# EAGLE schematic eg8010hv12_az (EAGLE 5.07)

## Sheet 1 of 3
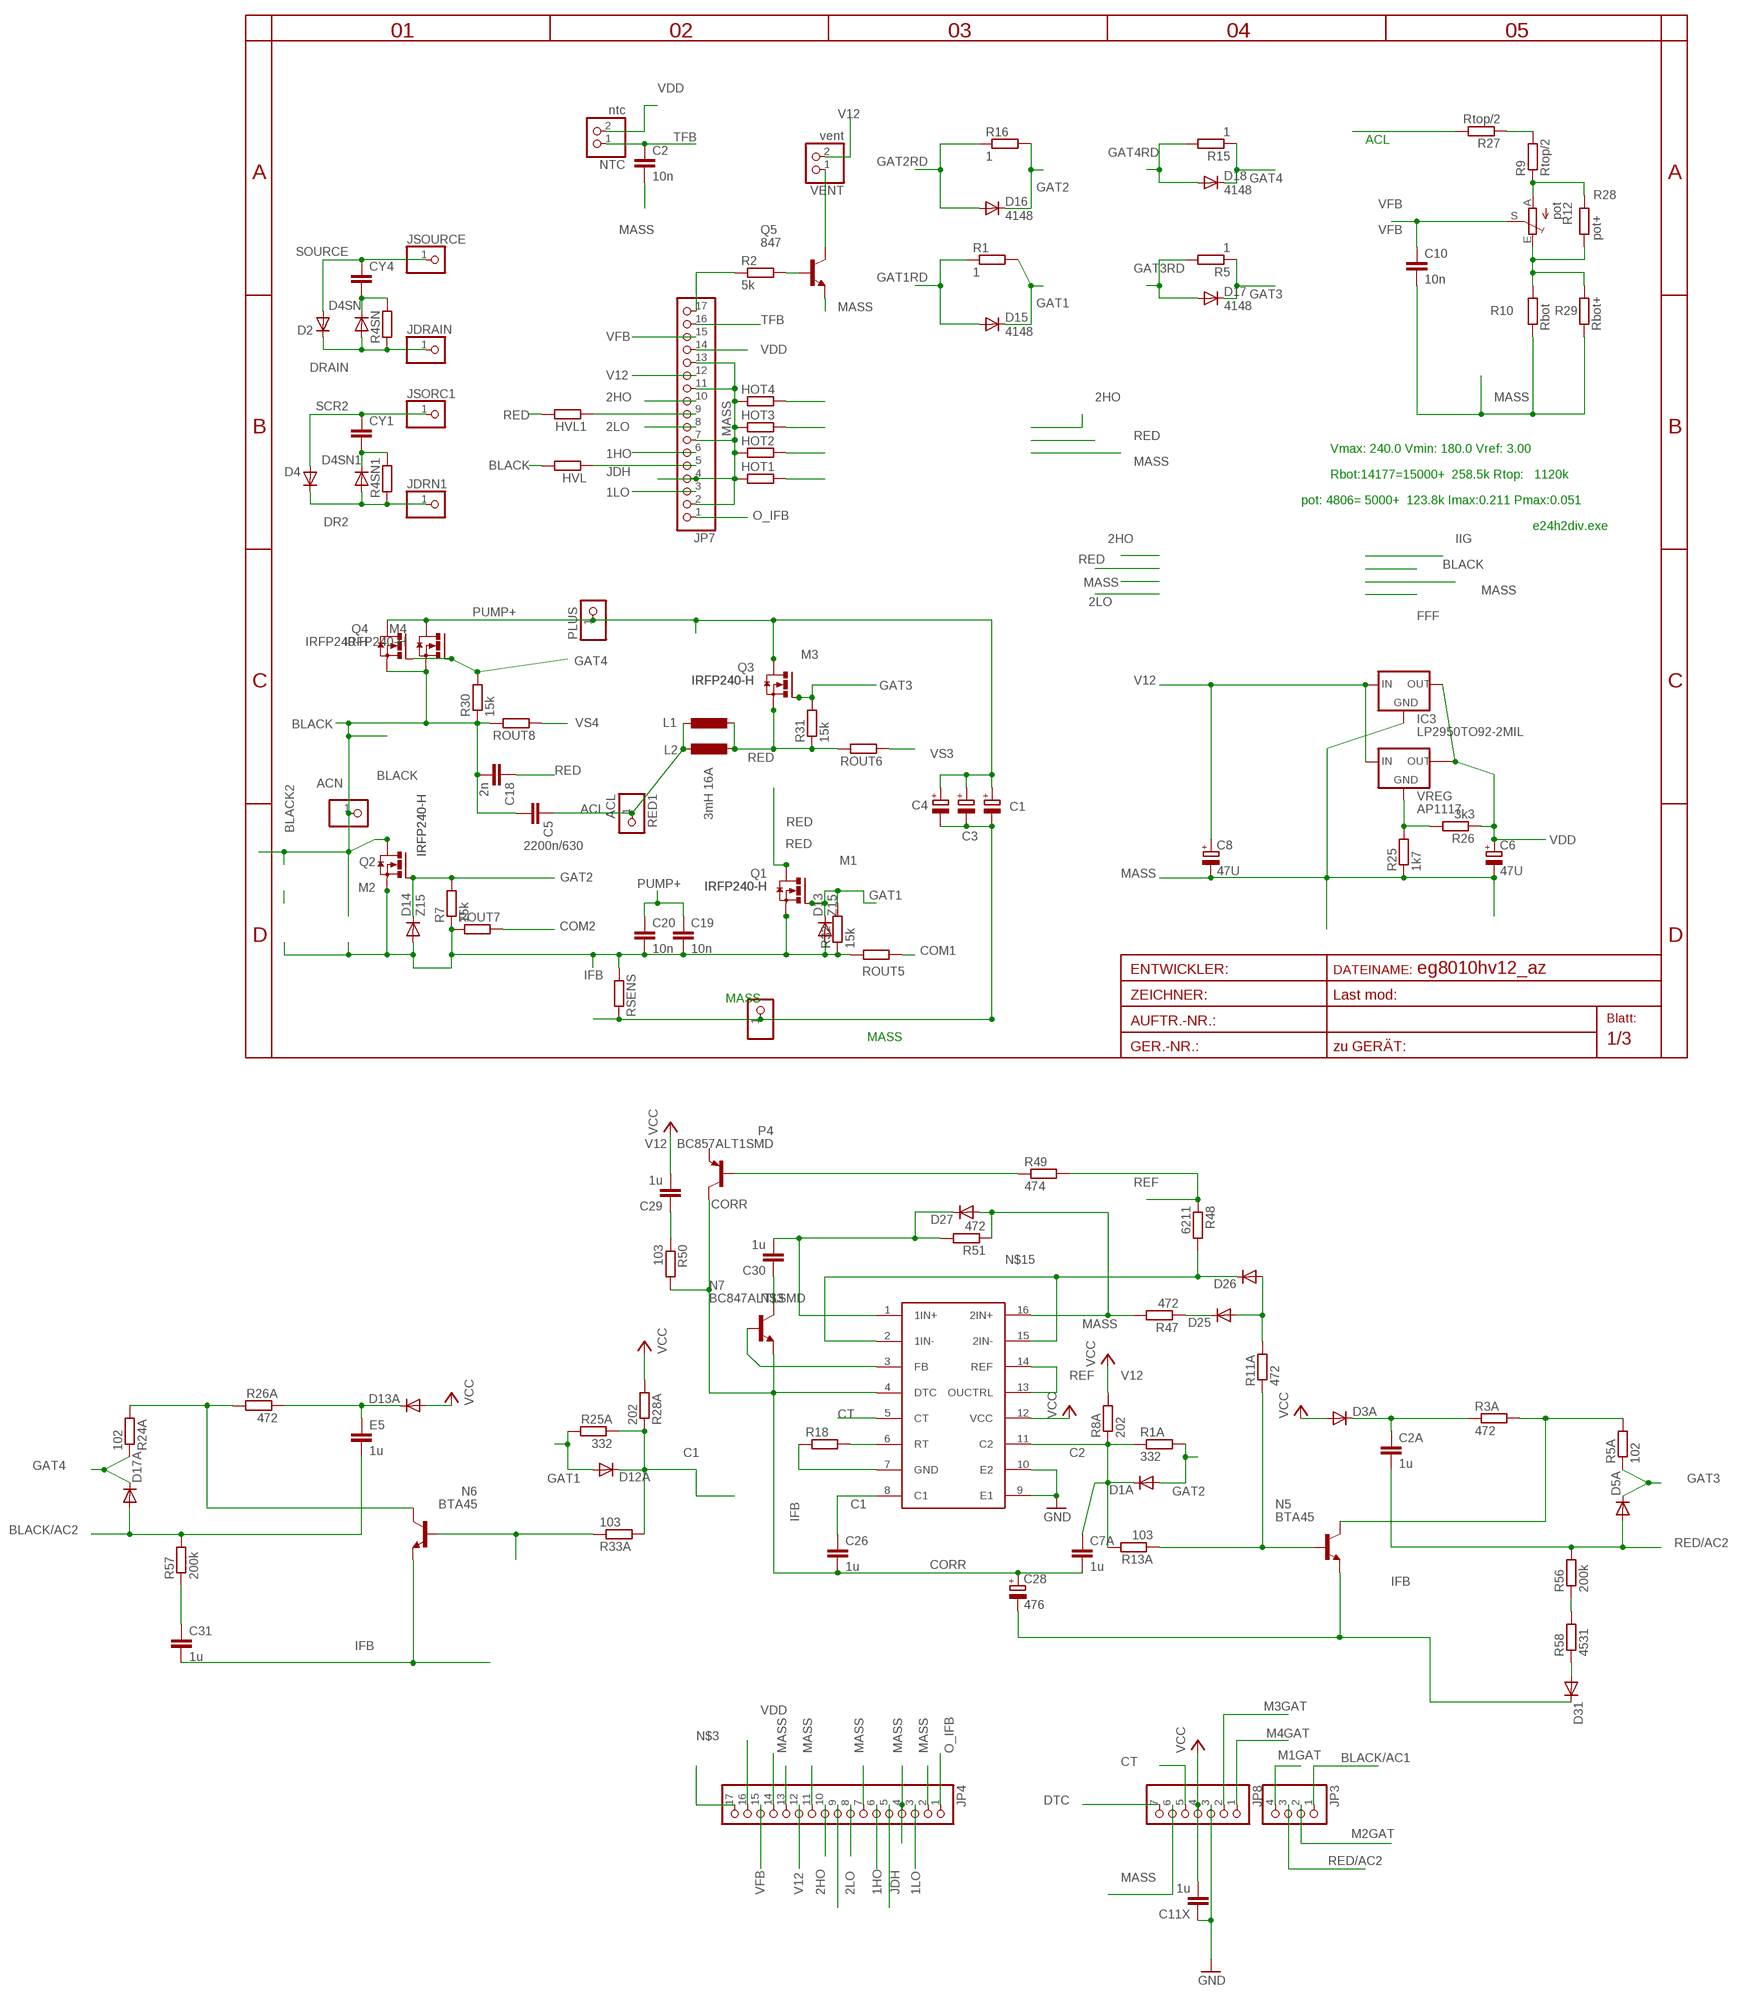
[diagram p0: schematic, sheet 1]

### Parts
BLACK2  ACN  PINHD-1X12MM3  [1X2MM3]
C1  CPOL-EUE5-13  [E5-13]
C2  10n  C-EUC0805  [C0805]
C2A  1u  C-EUC1206  [C1206]
C3  CPOL-EUE5-13  [E5-13]
C4  CPOL-EUE5-13  [E5-13]
C5  2200n/630  C-EU275-173X316  [C275-173X316]
C6  47U  CPOL-EUSMCA  [SMC_A]
C7A  1u  C-EUC0805  [C0805]
C8  47U  CPOL-EUSMCA  [SMC_A]
C10  10n  C-EUC0805  [C0805]
C11X  1u  C-EUC1206  [C1206]
C18  2n  C-EU050-024X044  [C050-024X044]
C19  10n  C-EU050-024X044  [C050-024X044]
C20  10n  C-EU050-024X044  [C050-024X044]
C26  1u  C-EUC0805  [C0805]
C28  476  CPOL-EUD  [PANASONIC_D]
C29  1u  C-EUC0805  [C0805]
C30  1u  C-EUC0805  [C0805]
C31  1u  C-EUC1206  [C1206]
CY1  CXXC10B5  [XC10B5]
CY4  CXXC10B5  [XC10B5]
D1A  DIODE-MINIMELF  [MINIMELF]
D2  DIODE-SMC  [SMC]
D3A  DIODE-SMA-DO214  [SMA-DO214AC]
D4  DIODE-SMC  [SMC]
D4SN  DIODE-P1-10  [P1-10]
D4SN1  DIODE-P1-10  [P1-10]
D5A  DIODE-MINIMELF  [MINIMELF]
D12A  DIODE-MINIMELF  [MINIMELF]
D13  Z15  DIODE-MINIMELF  [MINIMELF]
D13A  DIODE-SMA-DO214  [SMA-DO214AC]
D14  Z15  DIODE-MINIMELF  [MINIMELF]
D15  4148  DIODE-MINIMELF  [MINIMELF]
D16  4148  DIODE-MINIMELF  [MINIMELF]
D17  4148  DIODE-MINIMELF  [MINIMELF]
D17A  DIODE-MINIMELF  [MINIMELF]
D18  4148  DIODE-MINIMELF  [MINIMELF]
D25  DIODE-MINIMELF  [MINIMELF]
D26  DIODE-MINIMELF  [MINIMELF]
D27  DIODE-MINIMELF  [MINIMELF]
D31  DIODE-MINIMELF  [MINIMELF]
E5  1u  C-EUC1206  [C1206]
HOT1  R-EU_R0805  [R0805]
HOT2  R-EU_R0805  [R0805]
HOT3  R-EU_R0805  [R0805]
HOT4  R-EU_R0805  [R0805]
HVL  R-EU_R1005  [R1005]
HVL1  R-EU_R1005  [R1005]
IC3  LP2950TO92-2MIL  [TO92-2MIL]
JDRAIN  PINHD-1X11MM0  [1X1MM0]
JDRN1  PINHD-1X11MM0  [1X1MM0]
JP3  PINHD-1X4  [1X04]
JP4  PINHD-1X17  [1X17]
JP7  PINHD-1X17  [1X17]
JP8  PINHD-1X7  [1X07]
JSORC1  PINHD-1X11MM0  [1X1MM0]
JSOURCE  PINHD-1X11MM0  [1X1MM0]
L1  L-EU4.13  [0204/13]
L2  3mH 16A  L-EURNG  [RING]
M1  IRFP240-H  [TO247BH]
M2  IRFP240-H  [TO247BH]
M3  IRFP240-H  [TO247BH]
M4  IRFP240-H  [TO247BH]
MINUS  PINHD-1X12MM3  [1X2MM3]
N5  BTA45  SMBTA45HV  [SOT23HV]
N6  BTA45  SMBTA45HV  [SOT23HV]
N7  BC847ALT1SMD  [SOT23]
NTC  ntc  PINHD-1X2STR  [1X02]
P4  BC857ALT1SMD  [SOT23-BEC]
PLUS  PINHD-1X12MM3  [1X2MM3]
Q1  IRFP240-H  [TO247BH]
Q2  IRFP240-H  [TO247BH]
Q3  IRFP240-H  [TO247BH]
Q4  IRFP240-H  [TO247BH]
Q5  847  BC847SMD  [SOT23]
R1  1  R-EU_R2512  [R2512]
R1A  332  R-EU_R0805  [R0805]
R2  5k  R-EU_R0805  [R0805]
R3A  472  R-EU_R0805  [R0805]
R4SN  R-EU_0207/10  [0207/10]
R4SN1  R-EU_0207/10  [0207/10]
R5  1  R-EU_R2512  [R2512]
R5A  102  R-EU_R1206  [R1206]
R7  15k  R-EU_R1206  [R1206]
R8A  202  R-EU_R0805  [R0805]
R9  Rtop/2  R-EU_R1206  [R1206]
R10  Rbot  R-EU_R0805  [R0805]
R11A  472  R-EU_R0805  [R0805]
R12  pot  TRIM_EU-B64Y  [B64Y]
R13A  103  R-EU_0207/15  [0207/15]
R15  1  R-EU_R2512  [R2512]
R16  1  R-EU_R2512  [R2512]
R18  R-EU_R0805  [R0805]
R24A  102  R-EU_R1206  [R1206]
R25  1k7  R-EU_R0805  [R0805]
R25A  332  R-EU_R0805  [R0805]
R26  3k3  R-EU_R0805  [R0805]
R26A  472  R-EU_R0805  [R0805]
R27  Rtop/2  R-EU_R1206  [R1206]
R28  pot+  R-EU_R0805  [R0805]
R28A  202  R-EU_R0805  [R0805]
R29  Rbot+  R-EU_R0805  [R0805]
R30  15k  R-EU_R1206  [R1206]
R31  15k  R-EU_R1206  [R1206]
R32  15k  R-EU_R1206  [R1206]
R33A  103  R-EU_0207/15  [0207/15]
R47  472  R-EU_R0805  [R0805]
R48  6211  R-EU_R1206  [R1206]
R49  474  R-EU_R1206  [R1206]
R50  103  R-EU_R1206  [R1206]
R51  472  R-EU_R0805  [R0805]
R56  200k  R-EU_R0805  [R0805]
R57  200k  R-EU_R0805  [R0805]
R58  4531  R-EU_R0805  [R0805]
RED1  ACL  PINHD-1X12MM3  [1X2MM3]
ROUT5  R-EU_R2512  [R2512]
ROUT6  R-EU_R2512  [R2512]
ROUT7  R-EU_R2512  [R2512]
ROUT8  R-EU_R2512  [R2512]
RSENS  R-EU_WIRE  [WIRE]
U$5  AZ7500SO16  [SO16]
VENT  vent  PINHD-1X2STR  [1X02]
VREG  AP1117  [SOT223]

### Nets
1HO: HOT2.2 JP4.6 JP7.6 ; also sheet 3
1LO: HOT1.2 JP4.3 JP7.3 ; also sheet 3
2HO: HOT4.2 JP4.10 JP7.10 ; also sheet 3
2LO: HOT3.2 JP4.8 JP7.8 ; also sheet 3
ACL: C5.1 L1.1 L2.2 R27.2 RED1.1
BLACK: BLACK2.1 C5.2 C18.2 HVL.2 M2.D M4.S Q2.D Q4.S R30.1 ROUT8.2
BLACK/AC1: JP3.1
BLACK/AC2: D17A.A E5.2 R57.2
C1: C26.1 D12A.C R25A.1 R28A.1 R33A.2 U$5.8(C1)
C2: C7A.1 D1A.C R1A.1 R8A.1 R13A.2 U$5.11(C2)
COM1: ROUT5.1 ; also sheet 3
COM2: ROUT7.2 ; also sheet 3
CORR: C7A.2 C26.2 C28.+ N7.2(E) P4.C R50.2 U$5.4(DTC)
CT: JP8.5 U$5.5(CT)
DFG: HVL1.1 JP7.9
DFG1: JP4.9
DR2: D4.C D4SN1.A JDRN1.1 R4SN1.1
DRAIN: D2.C D4SN.A JDRAIN.1 R4SN.1
DTC: JP8.7
GAT1: D12A.A D13.C D15.C M1.G Q1.G R1.2 R25A.2 R32.2
GAT1RD: D15.A R1.1 ; also sheet 3
GAT2: D1A.A D14.C D16.C M2.G Q2.G R1A.2 R7.2 R16.2
GAT2RD: D16.A R16.1 ; also sheet 3
GAT3: D5A.C D17.C M3.G Q3.G R5.1 R5A.1 R31.2
GAT3RD: D17.A R5.2 ; also sheet 3
GAT4: D17A.C D18.C M4.G Q4.G R15.1 R24A.1 R30.2
GAT4RD: D18.A R15.2 ; also sheet 3
GND: C11X.1 JP8.3 U$5.9(E1) U$5.10(E2) ; also sheet 2
IFB: C19.2 C20.2 C28.- C31.2 D13.A D14.A D31.C M1.S M2.S N5.2(E) N6.2(E) Q1.S Q2.S R7.1 R18.1 R32.1 ROUT5.2 ROUT7.1 RSENS.1 U$5.7(GND) ; also sheet 2,3
JDH: HVL.1 JP4.5 JP7.5
M1GAT: JP3.4
M2GAT: JP3.2
M3GAT: JP8.2
M4GAT: JP8.1
MASS: C1.- C2.2 C3.- C4.- C6.- C8.- C10.2 D27.A HOT1.1 HOT2.1 HOT3.1 HOT4.1 IC3.2(GND) JP4.2 JP4.4 JP4.7 JP4.11 JP4.13 JP7.2 JP7.4 JP7.7 JP7.11 JP7.13 JP8.6 MINUS.1 Q5.2(E) R10.1 R25.1 R29.1 R47.2 R51.1 RSENS.2 U$5.16(2IN+) ; also sheet 2,3
N$1: Q5.3(C) VENT.1
N$2: Q5.1(B) R2.2
N$3: C30.2 D27.C JP4.17 JP7.17 R2.1 R51.2 U$5.1(1IN+)
N$4: C2A.1 D3A.K(C) R3A.1
N$5: N5.3(C) R3A.2 R5A.2
N$11: N5.1(B) R11A.1 R13A.1
N$13: D25.A D26.A R11A.2
N$15: D26.C R48.2 U$5.2(1IN-) U$5.15(2IN-) ; also sheet 2
N$17: R25.2 R26.2 VREG.1(GND)
N$23: R9.2 R27.1
N$29: R10.2 R12.E R28.1 R29.2
N$30: R9.1 R12.A R28.2
N$36: D25.C R47.1
N$37: P4.B R49.1
N$38: R18.2 U$5.6(RT)
N$39: C29.1 R50.1
N$40: N7.1(B) U$5.3(FB)
N$41: C30.1 N7.3(C)
N$42: D13A.K(C) E5.1 R26A.1
N$43: N6.3(C) R24A.2 R26A.2
N$44: N6.1(B) R33A.1
N$45: C31.1 R57.1
N$46: R56.1 R58.2
N$47: D31.A R58.1
O_IFB: JP4.1 JP7.1 ; also sheet 3
PUMP+: C1.+ C3.+ C4.+ C19.1 C20.1 M3.D M4.D PLUS.1 Q3.D Q4.D ; also sheet 2
RED: C18.1 HVL1.2 L1.2 L2.1 M1.D M3.S Q1.D Q3.S R31.1 ROUT6.2
RED/AC2: C2A.2 D5A.A JP3.3 R56.2
REF: R48.1 R49.2 U$5.13(OUCTRL) U$5.14(REF)
SCR2: CY1.1 D4.A JSORC1.1
SNUB1: CY1.2 D4SN1.C R4SN1.2
SNUB2: CY4.2 D4SN.C R4SN.2
SOURCE: CY4.1 D2.A JSOURCE.1
TFB: C2.1 JP4.16 JP7.16 NTC.1 ; also sheet 2
V12: C8.+ C11X.2 C29.2 D3A.A D13A.A IC3.3(IN) JP4.12 JP7.12 JP8.4 R8A.2 R28A.2 U$5.12(VCC) VENT.2 VREG.3(IN) ; supply symbol labelled VCC ; also sheet 2,3
VDD: C6.+ IC3.1(OUT) JP4.14 JP7.14 NTC.2 R26.1 VREG.4(TAB) ; also sheet 2
VFB: C10.1 JP4.15 JP7.15 R12.S ; also sheet 2
VS3: ROUT6.1 ; also sheet 3
VS4: ROUT8.1 ; also sheet 3
Unconnected: P4.E VREG.2(OUT)

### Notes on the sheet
- Vmax: 240.0 Vmin: 180.0 Vref: 3.00
- Rbot:14177=15000+  258.5k Rtop:   1120k
- pot: 4806= 5000+  123.8k Imax:0.211 Pmax:0.051
- e24h2div.exe

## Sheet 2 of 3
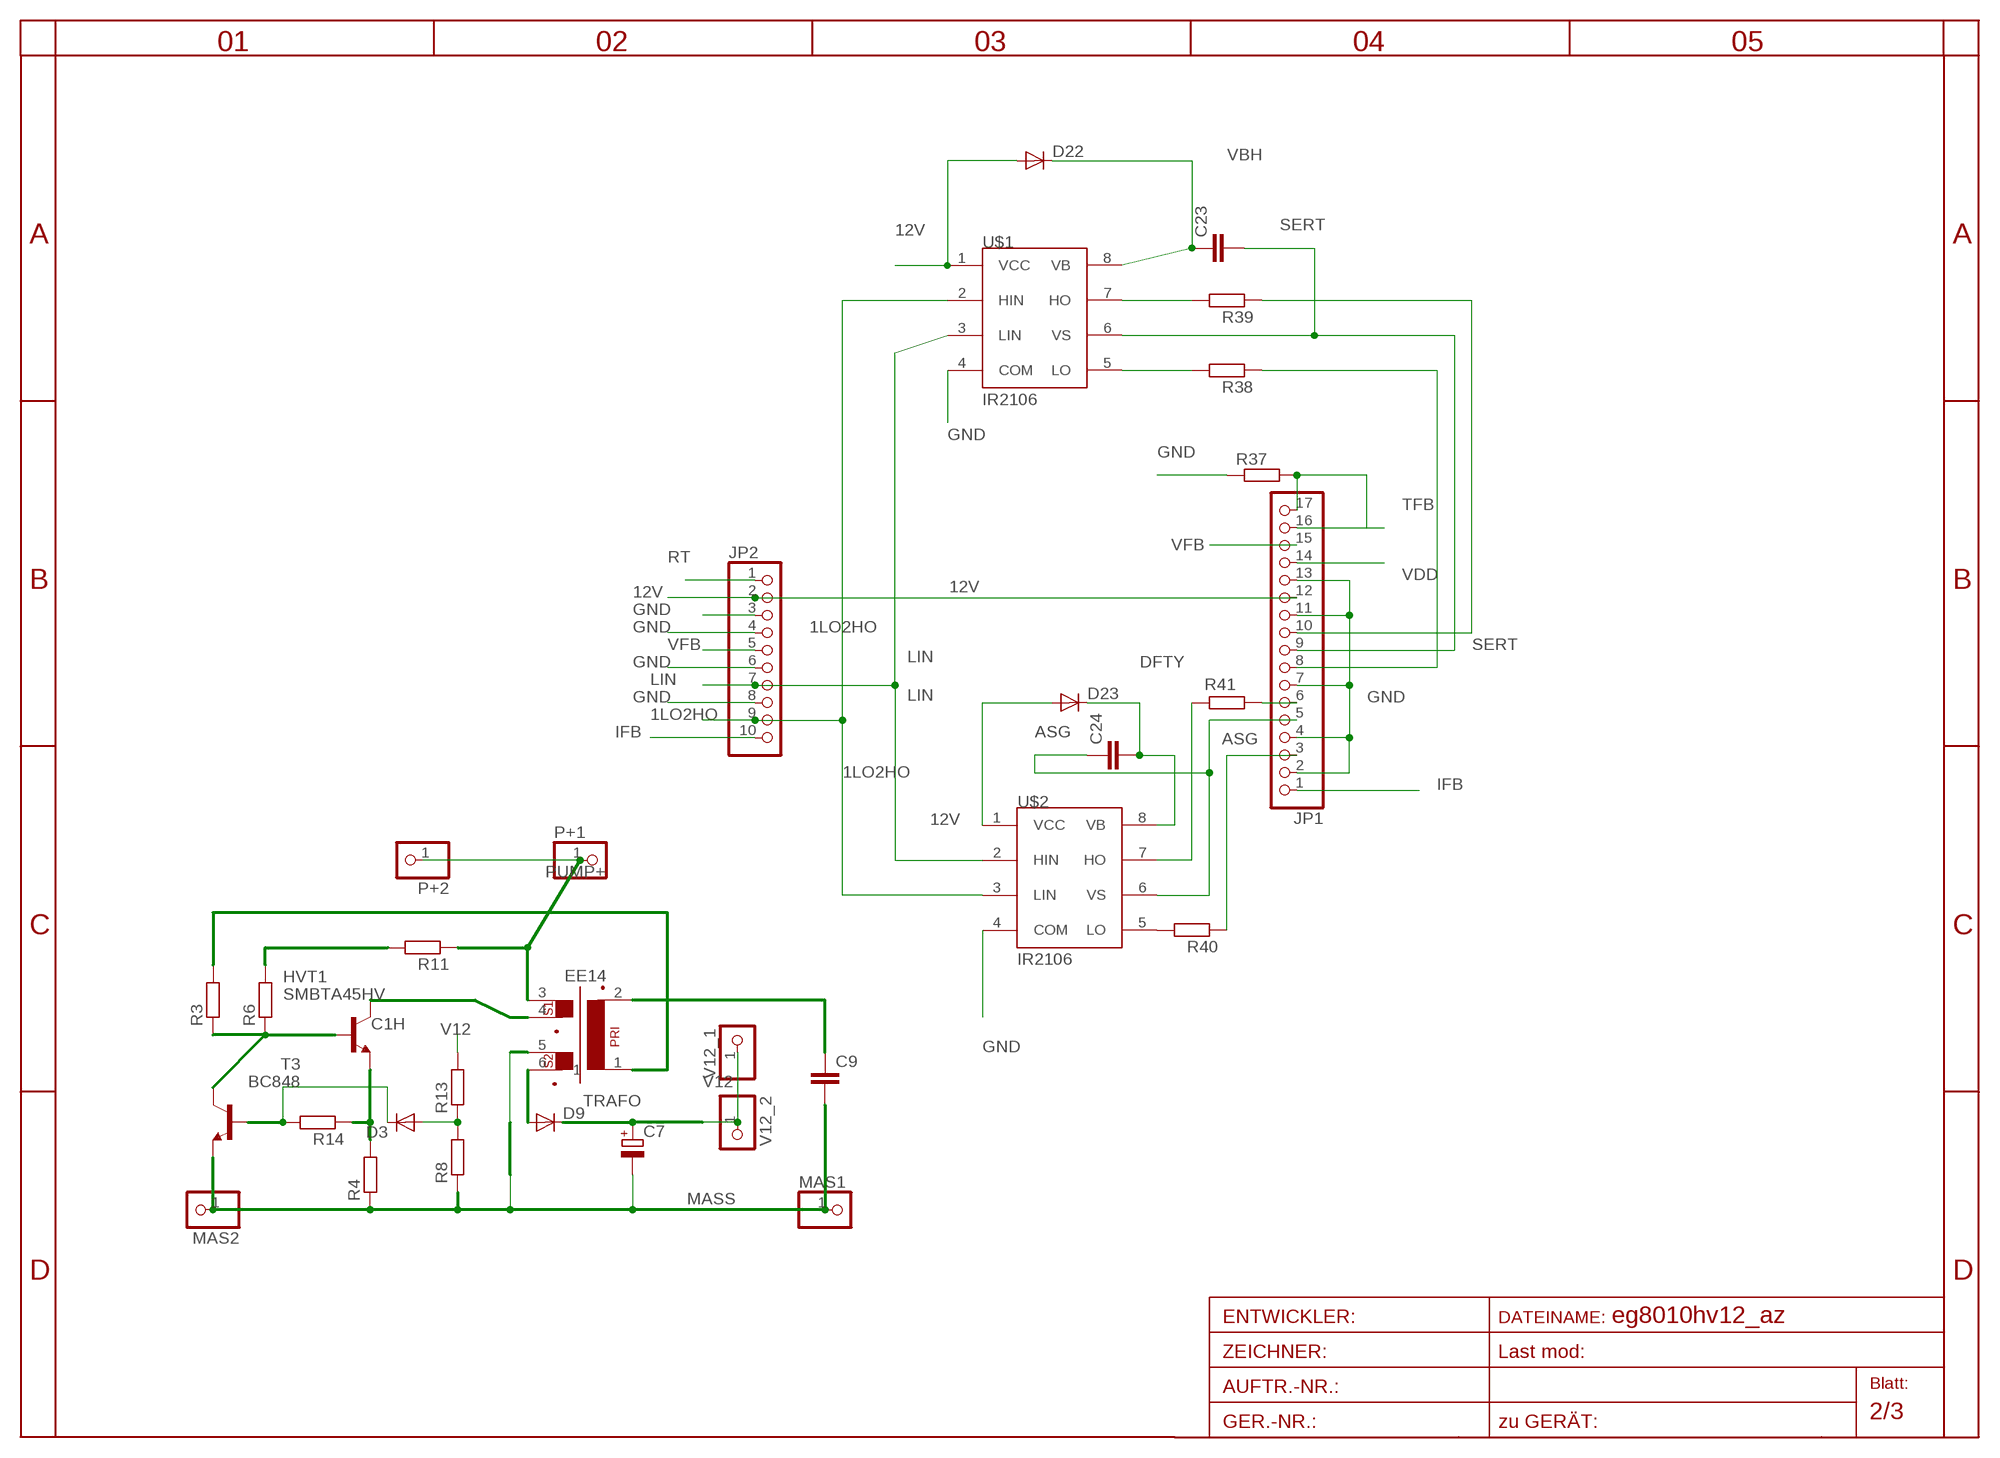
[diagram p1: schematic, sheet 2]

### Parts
C7  CPOL-EUSMCA  [SMC_A]
C9  C-EUC0805  [C0805]
C23  C-EUC1206  [C1206]
C24  C-EUC1206  [C1206]
D3  DIODE-MINIMELF  [MINIMELF]
D9  DIODE-SMA-DO214  [SMA-DO214AC]
D22  DIODE-SMA-DO214  [SMA-DO214AC]
D23  DIODE-SMA-DO214  [SMA-DO214AC]
HVT1  SMBTA45HV  [SOT23HV]
JP1  PINHD-1X17  [1X17]
JP2  PINHD-1X100X05  [1X10]
MAS1  PINHD-1X11X0.4  [1X01]
MAS2  PINHD-1X11X0.4  [1X01]
P+1  PINHD-1X11X0.4  [1X01]
P+2  PINHD-1X11X0.4  [1X01]
R3  R-EU_R0805  [R0805]
R4  R-EU_R0805  [R0805]
R6  R-EU_R1206  [R1206]
R8  R-EU_R0805  [R0805]
R11  R-EU_R1206  [R1206]
R13  R-EU_R0805  [R0805]
R14  R-EU_R0805  [R0805]
R37  R-EU_0204/2V  [0204V]
R38  R-EU_R1206  [R1206]
R39  R-EU_R1206  [R1206]
R40  R-EU_R1206  [R1206]
R41  R-EU_R1206  [R1206]
T3  BC848  [SOT23]
TRAFO  EE14  [EE14]
U$1  IR2106  [SO8-5]
U$2  IR2106  [SO8-5]
V12_1  PINHD-1X11X0.4  [1X01]
V12_2  PINHD-1X11X0.4  [1X01]

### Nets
1LO2HO: JP2.9 U$1.2(HIN) U$2.3(LIN)
12V: D22.A D23.A JP1.12 JP2.2 U$1.1(VCC) U$2.1(VCC)
A: D9.A TRAFO.6
ASG: C24.1 JP1.5 U$2.6(VS)
B1C2: HVT1.1(B) R3.1 R6.1 T3.C
BT1: D3.C R14.2 T3.B
C1H: HVT1.3(C) TRAFO.4
DFTY: C24.2 D23.K(C) U$2.8(VB)
EB: HVT1.2(E) R4.2 R14.1
GND: JP1.2 JP1.4 JP1.7 JP1.11 JP1.13 JP2.3 JP2.4 JP2.6 JP2.8 R37.1 U$1.4(COM) U$2.4(COM) ; also sheet 1
IFB: JP1.1 JP2.10 ; also sheet 1,3
LIN: JP2.7 U$1.3(LIN) U$2.2(HIN)
MASS: C7.- C9.2 MAS1.1 MAS2.1 R4.1 R8.1 T3.E TRAFO.5 ; also sheet 1,3
N$6: R3.2 TRAFO.1
N$7: C9.1 TRAFO.2
N$8: R6.2 R11.2
N$10: D3.A R8.2 R13.1
N$15: JP1.3 R40.1 ; also sheet 1
N$19: R41.2 U$2.7(HO)
N$21: JP1.8 R38.1
N$27: JP1.10 R39.1
N$32: R38.2 U$1.5(LO)
N$33: R39.2 U$1.7(HO)
N$34: JP1.6 R41.1
N$35: R40.2 U$2.5(LO)
PUMP+: P+1.1 P+2.1 R11.1 TRAFO.3 ; also sheet 1
RT: JP2.1
SERT: C23.2 JP1.9 U$1.6(VS)
TFB: JP1.16 JP1.17 R37.2 ; also sheet 1
V12: C7.+ D9.K(C) R13.2 V12_1.1 V12_2.1 ; also sheet 1,3
VBH: C23.1 D22.K(C) U$1.8(VB)
VDD: JP1.14 ; also sheet 1
VFB: JP1.15 JP2.5 ; also sheet 1

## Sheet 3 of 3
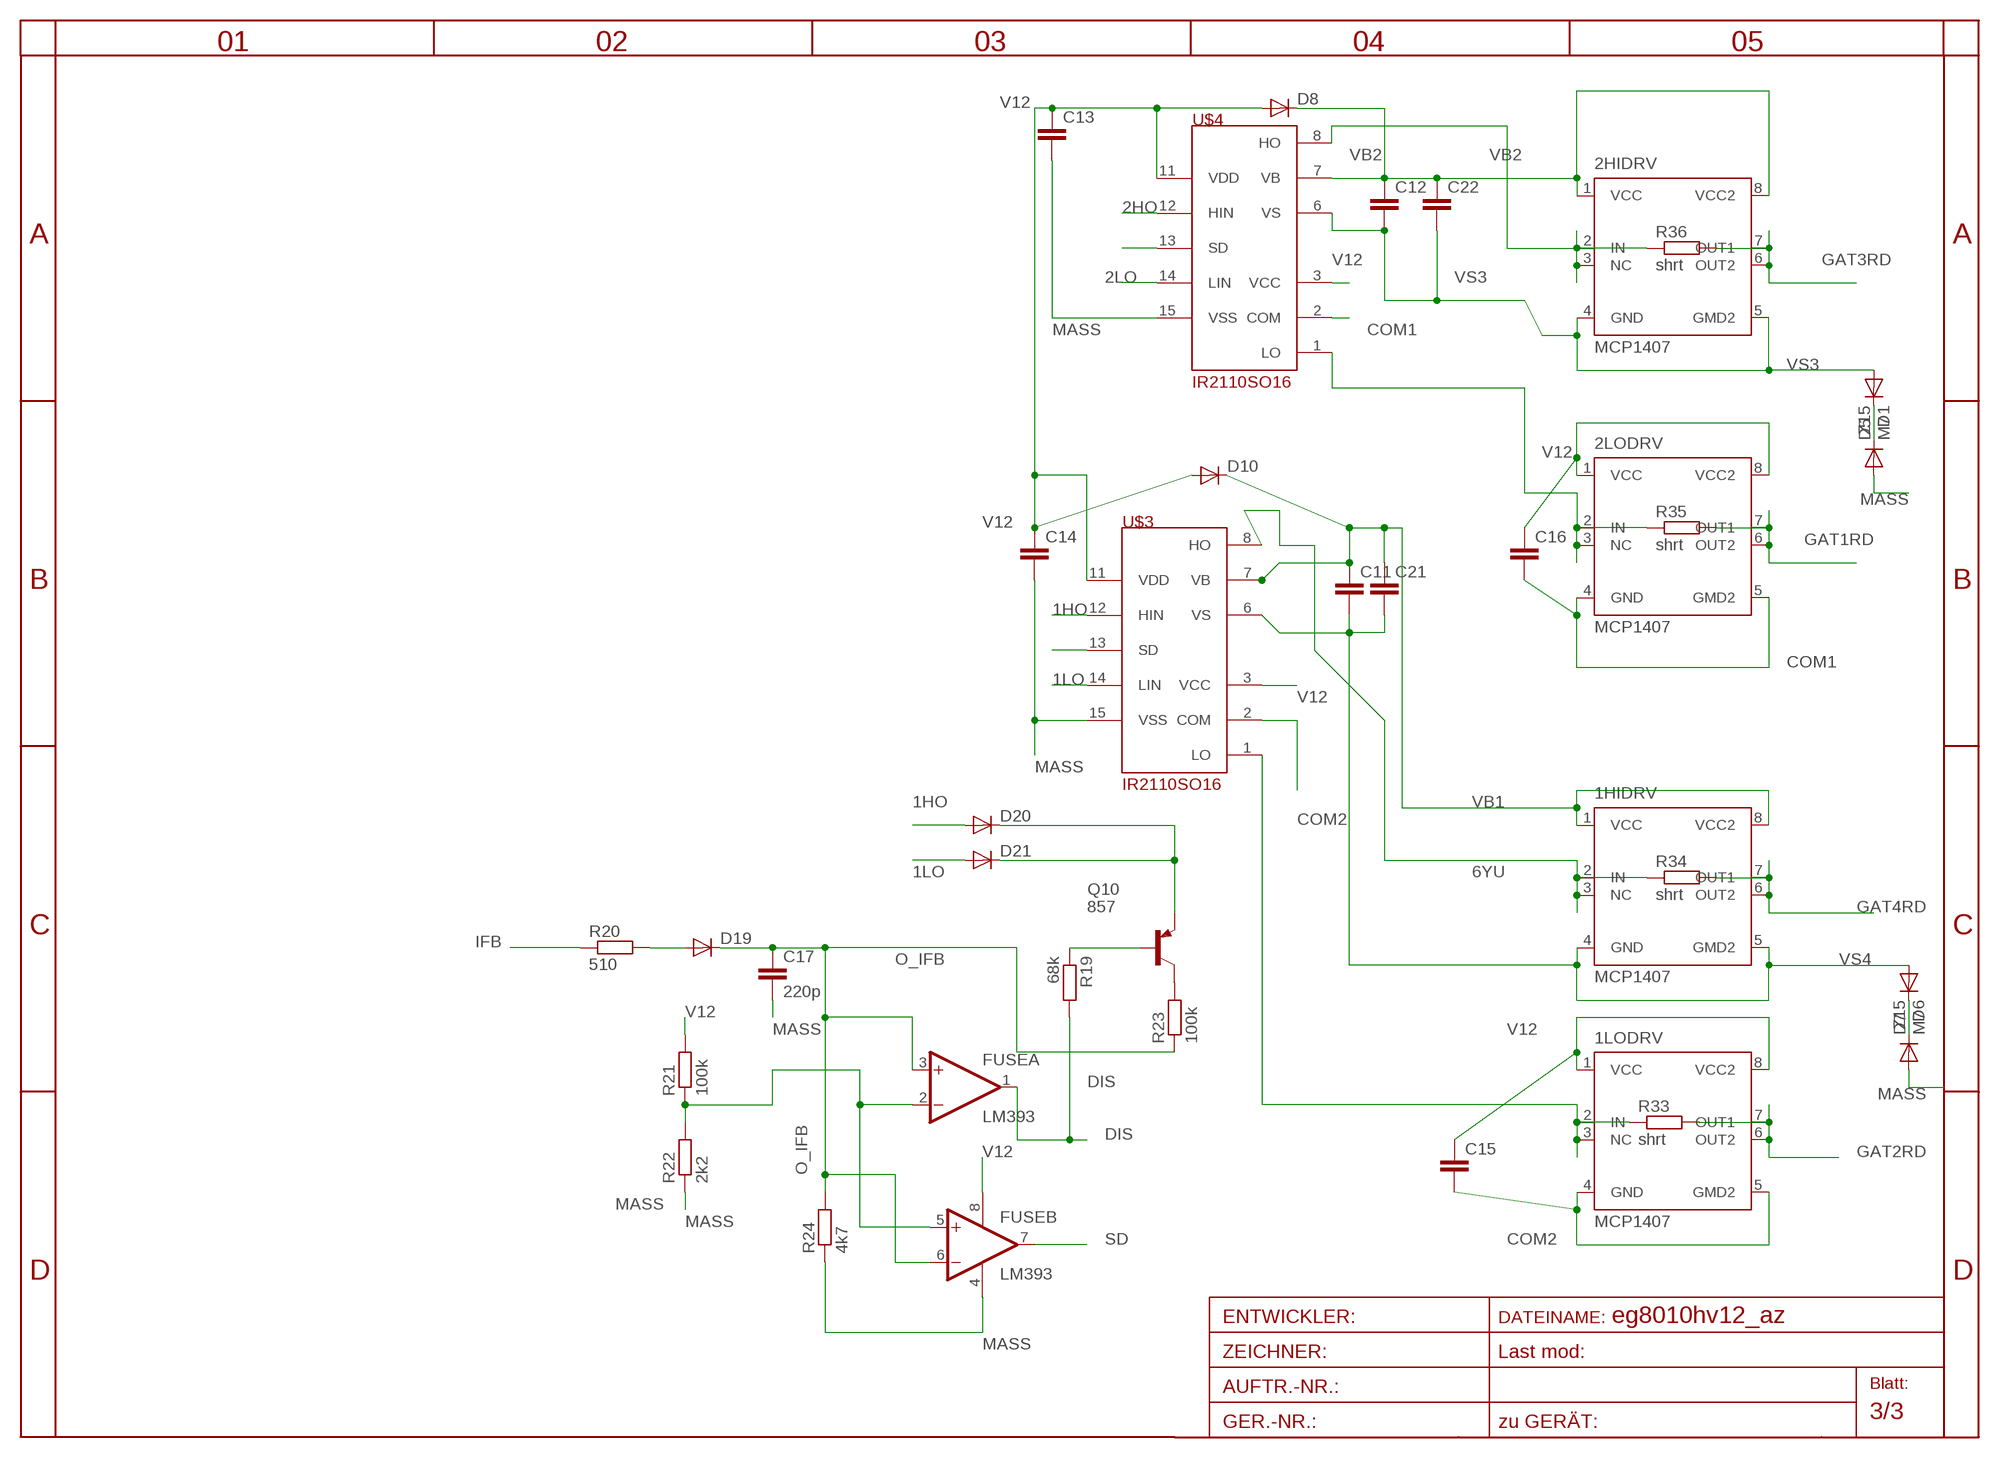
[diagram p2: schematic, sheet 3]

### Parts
1HIDRV  MCP1407  [SO-08M]
1LODRV  MCP1407  [SO-08M]
2HIDRV  MCP1407  [SO-08M]
2LODRV  MCP1407  [SO-08M]
C11  C-EUC058MLCC  [C058-020X040]
C12  C-EUC058MLCC  [C058-020X040]
C13  C-EUC1206  [C1206]
C14  C-EUC1206  [C1206]
C15  C-EUC1206  [C1206]
C16  C-EUC1206  [C1206]
C17  220p  C-EUC0805  [C0805]
C21  C-EUC1206  [C1206]
C22  C-EUC1206  [C1206]
D1  Z15  DIODE-MINIMELF  [MINIMELF]
D5  M7  DIODE-SMA-DO214  [SMA-DO214AC]
D6  Z15  DIODE-MINIMELF  [MINIMELF]
D7  M7  DIODE-SMA-DO214  [SMA-DO214AC]
D8  DIODE-SMA-DO214  [SMA-DO214AC]
D10  DIODE-SMA-DO214  [SMA-DO214AC]
D19  DIODE-SOT23  [SOT23]
D20  DIODE-SOT23  [SOT23]
D21  DIODE-SOT23  [SOT23]
FUSE  LM393  LM358D  [SO08]
Q10  857  BC857ALT1SMD  [SOT23-BEC]
R19  68k  R-EU_R0805  [R0805]
R20  510  R-EU_R0805  [R0805]
R21  100k  R-EU_R0805  [R0805]
R22  2k2  R-EU_R0805  [R0805]
R23  100k  R-EU_R0805  [R0805]
R24  4k7  R-EU_R0805  [R0805]
R33  shrt  R-EU_R1206  [R1206]
R34  shrt  R-EU_R1206  [R1206]
R35  shrt  R-EU_R1206  [R1206]
R36  shrt  R-EU_R1206  [R1206]
U$3  IR2110SO16  [SO16DW]
U$4  IR2110SO16  [SO16DW]

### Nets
1HO: D20.1(A) U$3.12(HIN) ; also sheet 1
1LO: D21.1(A) U$3.14(LIN) ; also sheet 1
2HO: U$4.12(HIN) ; also sheet 1
2LO: U$4.14(LIN) ; also sheet 1
6YU: 1HIDRV.2(IN) 1HIDRV.3(NC) R34.1 U$3.8(HO)
COM1: 2LODRV.4(GND) 2LODRV.5(GMD2) C16.2 U$4.2(COM) ; also sheet 1
COM2: 1LODRV.4(GND) 1LODRV.5(GMD2) C15.2 U$3.2(COM) ; also sheet 1
DIS: FUSE.1(A:OUT) R19.2
ET: 1LODRV.2(IN) 1LODRV.3(NC) R33.1 U$3.1(LO)
GAT1RD: 2LODRV.6(OUT2) 2LODRV.7(OUT1) R35.2 ; also sheet 1
GAT2RD: 1LODRV.6(OUT2) 1LODRV.7(OUT1) R33.2 ; also sheet 1
GAT3RD: 2HIDRV.6(OUT2) 2HIDRV.7(OUT1) R36.2 ; also sheet 1
GAT4RD: 1HIDRV.6(OUT2) 1HIDRV.7(OUT1) R34.2 ; also sheet 1
IFB: R20.1 ; also sheet 1,2
MASS: C13.2 C14.2 C17.2 D5.A D7.A FUSE.4(P:V-) R22.1 R24.1 U$3.15(VSS) U$4.15(VSS) ; also sheet 1,2
N$9: FUSE.2(A:-IN) FUSE.5(B:+IN) R21.1 R22.2
N$12: 2HIDRV.2(IN) 2HIDRV.3(NC) R36.1 U$4.8(HO)
N$14: D19.1(A) R20.2
N$16: 2LODRV.2(IN) 2LODRV.3(NC) R35.1 U$4.1(LO)
N$18: D20.3(C) D21.3(C) Q10.E
N$20: D1.C D5.K(C)
N$24: D6.C D7.K(C)
N$25: Q10.B R19.1
N$26: Q10.C R23.2
O_IFB: C17.1 D19.3(C) FUSE.3(A:+IN) FUSE.6(B:-IN) R23.1 R24.2 ; also sheet 1
SD: FUSE.7(B:OUT) U$3.13(SD) U$4.13(SD)
V12: 1LODRV.1(VCC) 1LODRV.8(VCC2) 2LODRV.1(VCC) 2LODRV.8(VCC2) C13.1 C14.1 C15.1 C16.1 D8.A D10.A FUSE.8(P:V+) R21.2 U$3.3(VCC) U$3.11(VDD) U$4.3(VCC) U$4.11(VDD) ; also sheet 1,2
VB1: 1HIDRV.1(VCC) 1HIDRV.8(VCC2) C11.1 C21.1 D10.K(C) U$3.7(VB)
VB2: 2HIDRV.1(VCC) 2HIDRV.8(VCC2) C12.1 C22.1 D8.K(C) U$4.7(VB)
VS3: 2HIDRV.4(GND) 2HIDRV.5(GMD2) C12.2 C22.2 D1.A U$4.6(VS) ; also sheet 1
VS4: 1HIDRV.4(GND) 1HIDRV.5(GMD2) C11.2 C21.2 D6.A U$3.6(VS) ; also sheet 1

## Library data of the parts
1HIDRV 1LODRV 2HIDRV 2LODRV = microchip:MCP1407
BLACK2 JDRAIN JDRN1 JSORC1 JSOURCE MAS1 MAS2 MINUS P+1 P+2 PLUS RED1 V12_1 V12_2 = pinhead:PINHD-1X1: PIN HEADER
C1 C3 C4 C6-C8 C28 = rcl:CPOL-EU: POLARIZED CAPACITOR, European symbol
C2 C2A C5 C7A C9-C11 C11X C12-C24 C26 C29-C31 E5 = rcl:C-EU: CAPACITOR, European symbol
CY1 CY4 = rcl:CX: X CAPACITOR
D1 D1A D2 D3 D3A D4 D4SN D4SN1 D5 D5A D6-D10 D12A D13 D13A D14-D17 D17A D18-D23 D25-D27 D31 = diode:DIODE-: DIODE
FUSE = linear:LM358: OP AMP also LM158; LM258; LM2904 Source: http://cache.national.com/ds/LM/LM158.pdf
HOT1-HOT4 HVL HVL1 R1 R1A R2 R3 R3A R4 R4SN R4SN1 R5 R5A R6-R8 R8A R11 R11A R13 R13A R14-R16 R18-R24 R24A R25A R26A R28A R30-R33 R33A R34-R41 R47-R51 R56-R58 ROUT5-ROUT8 RSENS = rcl:R-EU_: RESISTOR, European symbol
HVT1 N5 N6 = transistor-npn:SMBTA45
IC3 = v-reg:LP2950?*: Source: http://cache.national.com/ds/LP/LP2950.pdf
JP1 JP4 JP7 = pinhead:PINHD-1X17: PIN HEADER
JP2 = pinhead:PINHD-1X10: PIN HEADER
JP3 = pinhead:PINHD-1X4: PIN HEADER
JP8 = pinhead:PINHD-1X7: PIN HEADER
L1 L2 = rcl:L-EU: INDUCTOR, European symbol
M1-M4 Q1-Q4 = transistor-power:IRFP240: HEXFET Power MosFet Source: http://www.irf.com/
N7 Q5 = transistor-npn:BC847*: NPN Transistor
NTC VENT = pinhead:PINHD-1X2: PIN HEADER
P4 Q10 = transistor-pnp:BC857*: PNP Transistror
R9 R10 R25-R29 = rcl-2:R-EU_: RESISTOR, European symbol
R12 = pot:TRIM_EU-: POTENTIOMETER
T3 = transistor:BC848: NPN TRANSISTOR
TRAFO = trafo:EE14
U$1 U$2 = irf-2:IR2106
U$3 U$4 = ir2112:IR2110
U$5 = az7500:AZ7500
VREG = v-reg:AP1117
